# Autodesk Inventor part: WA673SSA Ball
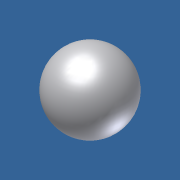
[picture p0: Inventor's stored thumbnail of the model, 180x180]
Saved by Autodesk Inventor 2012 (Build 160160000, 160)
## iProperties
Category: PARTsolutions
Created: 2011-07
Part Number: WA673SSA Ball
Catalog Web Link: www.cadenas.de
Description: Six types ball - Metric system sizes
Document SubType Name: Modeling
Designer: PARTsolutions
Density: 1 g/cm^3
Material: Par défaut
NB: WA673SSA Ball
NN: Six types ball
NT: Metric system sizes
NBSYN: $ORDER. Ball
LINA: WA673SSA Ball
SD: 3.0
D: 6
B: 2.0
R: 0.08
ORDER: WA673SSA
CR: 242
COR: 94
CRF: 25
CORF: 9,5
LSG: 60 000
LSO: 71 000
MASS: 0.20
ORDER1: 673
D1: 7.2
D2: 7.2
C1: 0.6
C2: 0.6
WSS: WA673SSA
WDS: SSA
UTWF: FL673
FORSS: FLWA673SA
FORDS: SSA
DA1: 3,6
DA2: 4,1
DA: 5,4
RAS: 0,08
MASS1: 0.26
B1: 2.5
VERS: 3
X: 1.500
N: 9
O: 14.130
RB: 0.444
KT: DUMMY
SUPPLIER: NTN
ARTICLENO: WA673SSA Ball
BOMINFO: WA673SSA Ball
CREATOR: CADENAS GmbH
PSOL_IDENT_0: {\\10.0.0.251\ps_data\23d-libs\ntn\ball_roller_bearings\miniature_extra_small_bb\metric_system_sizes
PSOL_IDENT_1: \mss_ball.prj},179 {VTYP=3D},{NB=WA673SSA Ball},{LINA=WA673SSA Ball},{NN=Six types ball},{DATE=11.12
PSOL_IDENT_2: .2007 08:48:23},{GEOMDATE=02.04.2007 00:00:00},{VERSION=},{LINEID=12590},{LINESUBID=-1},{WBVAR=}  {N
PSOL_IDENT_3: B=WA673SSA Ball},{LINA=WA673SSA Ball},{KT=DUMMY},{IDNR=},{SD=3.0},{D=6},{B=2.0},{R=0.08},{ORDER=WA67
PSOL_IDENT_4: 3SSA},{CR=242},{COR=94},{CRF=25},{CORF=9,5},{LSG=60 000},{LSO=71 000},{MASS=0.20},{ORDER1=673},{D1=7
PSOL_IDENT_5: .2},{D2=7.2},{C1=0.6},{C2=0.6},{WSS=WA673SSA},{WDS=SSA},{UTWF=FL673},{FORSS=FLWA673SA},{FORDS=SSA},{
PSOL_IDENT_6: DA1=3,6},{DA2=4,1},{DA=5,4},{RAS=0,08},{MASS1=0.26},{B1=2.5},{VERS=3},{X=1.5},{N=9},{O=14.13},{RB=0.
PSOL_IDENT_7: 444}
Title: WA673SSA Ball
Author: Cadenas PARTsolutions
Comments: Metric system sizes
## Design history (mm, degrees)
sketch "Sketch_1"
  geometry: L1 (0.444, 0)-(-0.444, 0); L2 (0.444, 0)-(-0.444, 0); A1 r 0.444 centre (0, 0) between (0.444, 0) and (-0.444, 0)
  constraints: 4 end point, 2 point on circle, 1 centre point
revolve "Revolution1" sketch "Sketch_1" stored, may be unused: angle "d0" = 360 deg
node "mss_ball_XY"
node "mss_ball_YZ"
node "mss_ball_ZX"
node "mss_ball_X"
node "mss_ball_Y"
node "mss_ball_Z"
node "mss_ball_Center"
node "Solide1"
node "Corps solides"
node "Corps surfaciques"
